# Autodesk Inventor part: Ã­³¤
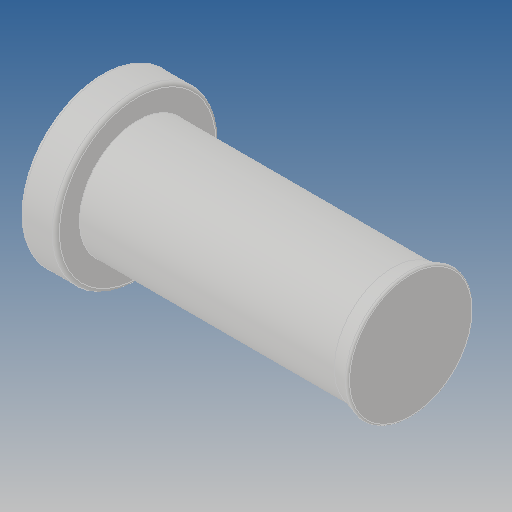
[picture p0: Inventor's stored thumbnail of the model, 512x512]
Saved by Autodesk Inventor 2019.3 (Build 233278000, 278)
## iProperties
Created: 2017-12
Part Number: Ã­³¤
Material: Ogólny
Document SubType Name: Modeling
Designer: Admin
Density: 1 g/cm^3
Appearance: Domyślna
Author: Admin
Revision Number: ÈÎºÎ
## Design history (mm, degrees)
feature "Ðý×ª1"
node "Bryła1"
